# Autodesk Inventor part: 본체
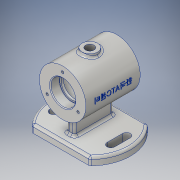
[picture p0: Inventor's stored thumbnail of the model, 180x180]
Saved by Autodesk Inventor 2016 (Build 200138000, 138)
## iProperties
Created: 2021-09
Part Number: 본체
Material: 알루미늄 6061
Document SubType Name: Modeling
Designer: Windows7
Mass: 467.933 g
Surface Area: 486.991 cm^2
Volume: 173.308 cm^3
Density: 2.7 g/cm^3
Appearance: 알루미늄 - 평지
Author: Windows7
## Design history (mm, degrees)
sketch "스케치1"
  geometry: L1 (0, 0)-(70, 0); L2 (70, 17)-(70, 30); L3 (70, 30)-(0, 30); L4 (0, 30)-(0, 17); L5 (1, 16)-(11.7, 16); L6 (12, 15.7)-(12, 14); L7 (12, 14)-(15, 14); L8 (15, 14)-(15, 22); L9 (18, 25)-(52, 25); L10 (55, 22)-(55, 14); L11 (55, 14)-(58, 14); L12 (58, 14)-(58, 15.7); L13 (58.3, 16)-(69, 16); L14 (1, 16)-(0, 17); L15 (70, 17)-(69, 16); A1 r 3 centre (18, 22) between (18, 25) and (15, 22); A2 r 3 centre (52, 22) between (55, 22) and (52, 25); A3 r 0.3 centre (11.7, 15.7) between (12, 15.7) and (11.7, 16); A4 r 0.3 centre (58.3, 15.7) between (58.3, 16) and (58, 15.7); 5 further points
  constraints: 30 end point, 16 point on line, 8 point on circle, 8 tangent, 7 perpendicular, 4 centre point, 2 equal radius, 2 horizontal, 2 parallel
  dimensions: "d0" = 60 diameter of L3 L1; "d1" = 70 distance between parallel lines of L2 L4; "d2" = 12 distance between parallel lines of L2 L12; "d3" = 32 diameter of L13 L1; "d4" = 28 diameter of L11 L1; "d5" = 50 diameter of L9 L1; "d6" = 3 distance between parallel lines of L12 L10; "d7" = 40 distance between parallel lines of L10 L8; "d8" = 3 distance between parallel lines of L8 L6; "d9" = 1 distance of L5.start point (0, 16); "d10" = 1 distance of L4.end point (0, 16) (= d9); "d11" = 1 distance of L2.start point (70, 16); "d12" = 1 distance of L13.end point (70, 16) (= d11); "d13" = 3 radius of A1; "d14" = 0.3 radius of A3
revolve "회전1" sketch "스케치1" stored, may be unused: angle "d15" = 90 deg
node "작업 평면1"
sketch "스케치3" dims "d22" = 46
  geometry: 5 further points
  constraints: 2 vertical alignment, 1 coincident, 6 other
  dimensions: "d25" = 360 deg dimension on point (0, 0) point (0, 23) (derived)
hole "구멍1" sketch "스케치3" at (0, 23), (-19.919, -11.5), (19.919, -11.5) diameter "d27" = 3.242; stored, may be unused: countersink angle "d31" = 90 deg, drill point angle "d33" = 118 deg; dims "d28" = 8, "d29" = 4, "d30" = 2, "d32" = 10
sketch "스케치4" dims "d34" = 46
  geometry: 5 further points
  constraints: 2 vertical alignment, 1 coincident, 6 other
  dimensions: "d37" = 360 deg dimension on point (0, 0) point (0, 23) (derived)
hole "구멍2" sketch "스케치4" at (0, 23), (-19.919, -11.5), (19.919, -11.5) diameter "d39" = 3.242; stored, may be unused: countersink angle "d43" = 90 deg, drill point angle "d45" = 118 deg; dims "d40" = 8, "d41" = 4, "d42" = 2, "d44" = 10
node "작업 평면2"
sketch "스케치5"
  geometry: C1 r 10 at (-35, 0); 1 further point
  constraints: 1 centre point, 1 horizontal alignment
  dimensions: "d47" = 20 diameter of C1; "d48" = 35 distance of point (0, 0) C1.centre
extrude "돌출1" join sketch "스케치5" stored distance "d49" = 10; taper "d50" = 0 deg
sketch "스케치6"
  geometry: 2 further points
  constraints: 1 horizontal alignment
  dimensions: "d51" = 35 distance of point (-35, 0) point (0, 0)
hole "구멍3" sketch "스케치6" at (0, 0) diameter "d52" = 10.917; stored, may be unused: countersink angle "d56" = 90 deg, drill point angle "d58" = 118 deg; dims "d53" = 29, "d54" = 4, "d55" = 2, "d57" = 29
node "작업 평면3"
sketch "스케치7"
  geometry: L1 (35, -30)-(35, 30) reference; 3 further points
  constraints: 2 other
  dimensions: "d87" = 35 distance from line of L1 point (0, 0); "d88" = 30 vertical distance of point (0, 0) L1.end
feature "엠보싱1" sketch "스케치7" dims "d0" = 60, "d1" = 70, "d2" = 12, "d3" = 32, "d4" = 28, "d5" = 50, "d6" = 3, "d7" = 40, "d8" = 3, "d9" = 1, "d10" = 1 (= d9), "d11" = 1, "d12" = 1 (= d11), "d13" = 3, "d14" = 0.3, "d59" = 0.5, "d60" = 0
sketch "스케치8"
  geometry: 1 further point
sketch "스케치9"
  geometry: L1 (-70, 30)-(-70, -30) reference; L2 (0, 30)-(0, -30) reference; L3 (-55.955, -29.89)-(-52.479, -29.89) reference; L4 (-52.479, -29.89)-(-52.479, -29.947) reference; L5 (-53.016, -29.972)-(-53.016, -29.999) reference; L6 (-53.016, -29.999)-(-55.638, -29.999) reference; L7 (-55.638, -29.999)-(-55.638, -29.992) reference; L8 (-55.638, -29.992)-(-53.016, -29.992) reference; L9 (-53.016, -29.992)-(-53.016, -29.925) reference; L10 (-53.016, -29.925)-(-55.955, -29.925) reference; L11 (-55.955, -29.925)-(-55.955, -29.89) reference; L12 (-49.939, -29.933)-(-49.939, -29.823) reference; L13 (-49.825, -29.795)-(-49.393, -29.795) reference; L14 (-49.393, -29.795)-(-49.393, -29.933) reference; L15 (-49.393, -29.933)-(-49.939, -29.933) reference; L16 (-48.001, -29.956)-(-46.764, -29.956) reference; L17 (-46.764, -29.956)-(-46.764, -29.976) reference; L18 (-46.764, -29.976)-(-48.001, -29.976) reference; L19 (-48.001, -29.976)-(-48.001, -29.952) reference; L20 (-48.001, -29.952)-(-48.547, -29.952) reference; L21 (-48.547, -29.952)-(-48.547, -29.836) reference; L22 (-48.449, -29.805)-(-48.001, -29.805) reference; L23 (-48.001, -29.805)-(-48.001, -29.956) reference; L24 (-45.461, -29.834)-(-45.461, -29.96) reference; L25 (-45.323, -29.972)-(-44.924, -29.972) reference; L26 (-44.924, -29.972)-(-44.924, -29.783) reference; L27 (-44.924, -29.783)-(-50.11, -29.783) reference; L28 (-50.11, -29.783)-(-50.11, -29.834) reference; L29 (-50.11, -29.834)-(-45.461, -29.834) reference; L30 (-45.885, -29.83)-(-45.404, -29.83) reference; L31 (-42.18, -29.979)-(-42.726, -29.979) reference; L32 (-42.775, -29.977)-(-42.237, -29.977) reference; L33 (-34.414, -29.835)-(-34.959, -29.835) reference; L34 (-34.959, -29.835)-(-34.959, -29.907) reference; L35 (-34.959, -29.907)-(-36.832, -29.907) reference; L36 (-36.832, -29.907)-(-36.832, -29.863) reference; L37 (-36.832, -29.863)-(-32.55, -29.863) reference; L38 (-32.55, -29.863)-(-32.55, -29.907) reference; L39 (-32.55, -29.907)-(-34.414, -29.907) reference; L40 (-34.414, -29.907)-(-34.414, -29.835) reference; L41 (-25.06, -29.983)-(-22.886, -29.983) reference; L42 (-22.886, -29.983)-(-22.886, -29.997) reference; L43 (-22.886, -29.997)-(-26.232, -29.997) reference; L44 (-26.232, -29.997)-(-26.232, -29.987) reference; L45 (-26.232, -29.987)-(-24.864, -29.987) reference; L46 (-25.19, -29.812)-(-20.045, -29.812) reference; L47 (-20.045, -29.812)-(-20.045, -29.86) reference; L48 (-20.045, -29.86)-(-24.612, -29.86) reference; L49 (-24.27, -29.987)-(-19.027, -29.987) reference; L50 (-19.027, -29.987)-(-19.027, -29.997) reference; L51 (-19.027, -29.997)-(-22.341, -29.997) reference; L52 (-22.341, -29.997)-(-22.341, -29.983) reference; L53 (-22.341, -29.983)-(-19.906, -29.983) reference; L54 (-19.906, -29.983)-(-19.906, -29.964) reference; L55 (-19.906, -29.964)-(-24.506, -29.964) reference; L56 (-24.506, -29.964)-(-24.506, -29.787) reference; L57 (-24.506, -29.787)-(-25.06, -29.787) reference; L58 (-25.06, -29.787)-(-25.06, -29.983) reference; L59 (-26.867, -29.835)-(-27.445, -29.835) reference; L60 (-28.129, -29.972)-(-30.832, -29.972) reference; L61 (-31.499, -29.835)-(-32.077, -29.835) reference; L62 (-29.798, -29.863)-(-29.147, -29.863) reference; L63 (-10.943, -29.907)-(-10.943, -29.937) reference; L64 (-10.943, -29.937)-(-15.461, -29.937) reference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; C1 r 5.459 at (-35, 0) reference; A1 r 52.5 centre (-35, 0) between (2.754, 36.481) and (-72.246, 37); A2 r 52.5 centre (-35, 0) between (-72.246, -37) and (2.754, -36.481); 70 further points; 7 other entities
  constraints: 4 end point, 4 point on circle, 2 centre point, 2 coincident, 2 vertical, 2 vertical alignment, 76 other
  dimensions: "d64" = 52.5 radius of A1; "d65" = 52.5 radius of A2; "d66" = 75 distance between parallel lines of L93 L94; "d68" = 74 distance of L94.start L94.end
extrude "돌출2" join sketch "스케치9" distance "d69" = 10; taper "d70" = 0 deg
fillet "모깎기1" dims "d71" = 3
fillet "모깎기2" dims "d72" = 3
sketch "스케치10"
  geometry: L1 (9.746, 5)-(59.746, 5); L2 (59.746, 5)-(59.746, -5); L3 (59.746, -5)-(9.746, -5); L4 (9.746, -5)-(9.746, 5); L5 (-2.754, 35.248)-(-2.754, -35.248) reference; 2 further points
  constraints: 8 end point, 2 parallel, 1 horizontal, 1 horizontal alignment, 1 midpoint, 1 perpendicular
  dimensions: "d73" = 50 distance between parallel lines of L2 L4; "d74" = 10 distance between parallel lines of L3 L1; "d75" = 12.5 distance between parallel lines of L4 L5
extrude "돌출3" join sketch "스케치10" stored distance "d76" = 10; taper "d77" = 0 deg
fillet "모깎기3" dims "d78" = 3
fillet "모깎기4" dims "d79" = 3
sketch "스케치11"
  geometry: L1 (24.746, -37)-(44.746, -37); L2 (24.746, -32)-(44.746, -32); L3 (44.746, -42)-(24.746, -42); L4 (-2.754, 35.248)-(-2.754, -35.248) reference; A1 r 5 centre (24.746, -37) between (24.746, -32) and (24.746, -42); A2 r 5 centre (44.746, -37) between (44.746, -42) and (44.746, -32); 2 further points
  constraints: 8 end point, 4 point on circle, 4 tangent, 2 centre point, 1 horizontal, 1 midpoint, 1 parallel
  dimensions: "d80" = 10 distance between parallel lines of L2 L3; "d81" = 37.5 distance from line of L4 point (34.746, -37); "d82" = 20 distance of L1.start L1.end; "d83" = 37 distance from line of point (0, 0) L1
extrude "돌출4" cut sketch "스케치11" stored distance "d84" = 10; taper "d85" = 0 deg
fillet "모깎기5" dims "d86" = 3
node "솔리드1"
mirror "대칭1"
node "투영된 루프1"
other parameters: "d16" = -62, "d46" = 33
